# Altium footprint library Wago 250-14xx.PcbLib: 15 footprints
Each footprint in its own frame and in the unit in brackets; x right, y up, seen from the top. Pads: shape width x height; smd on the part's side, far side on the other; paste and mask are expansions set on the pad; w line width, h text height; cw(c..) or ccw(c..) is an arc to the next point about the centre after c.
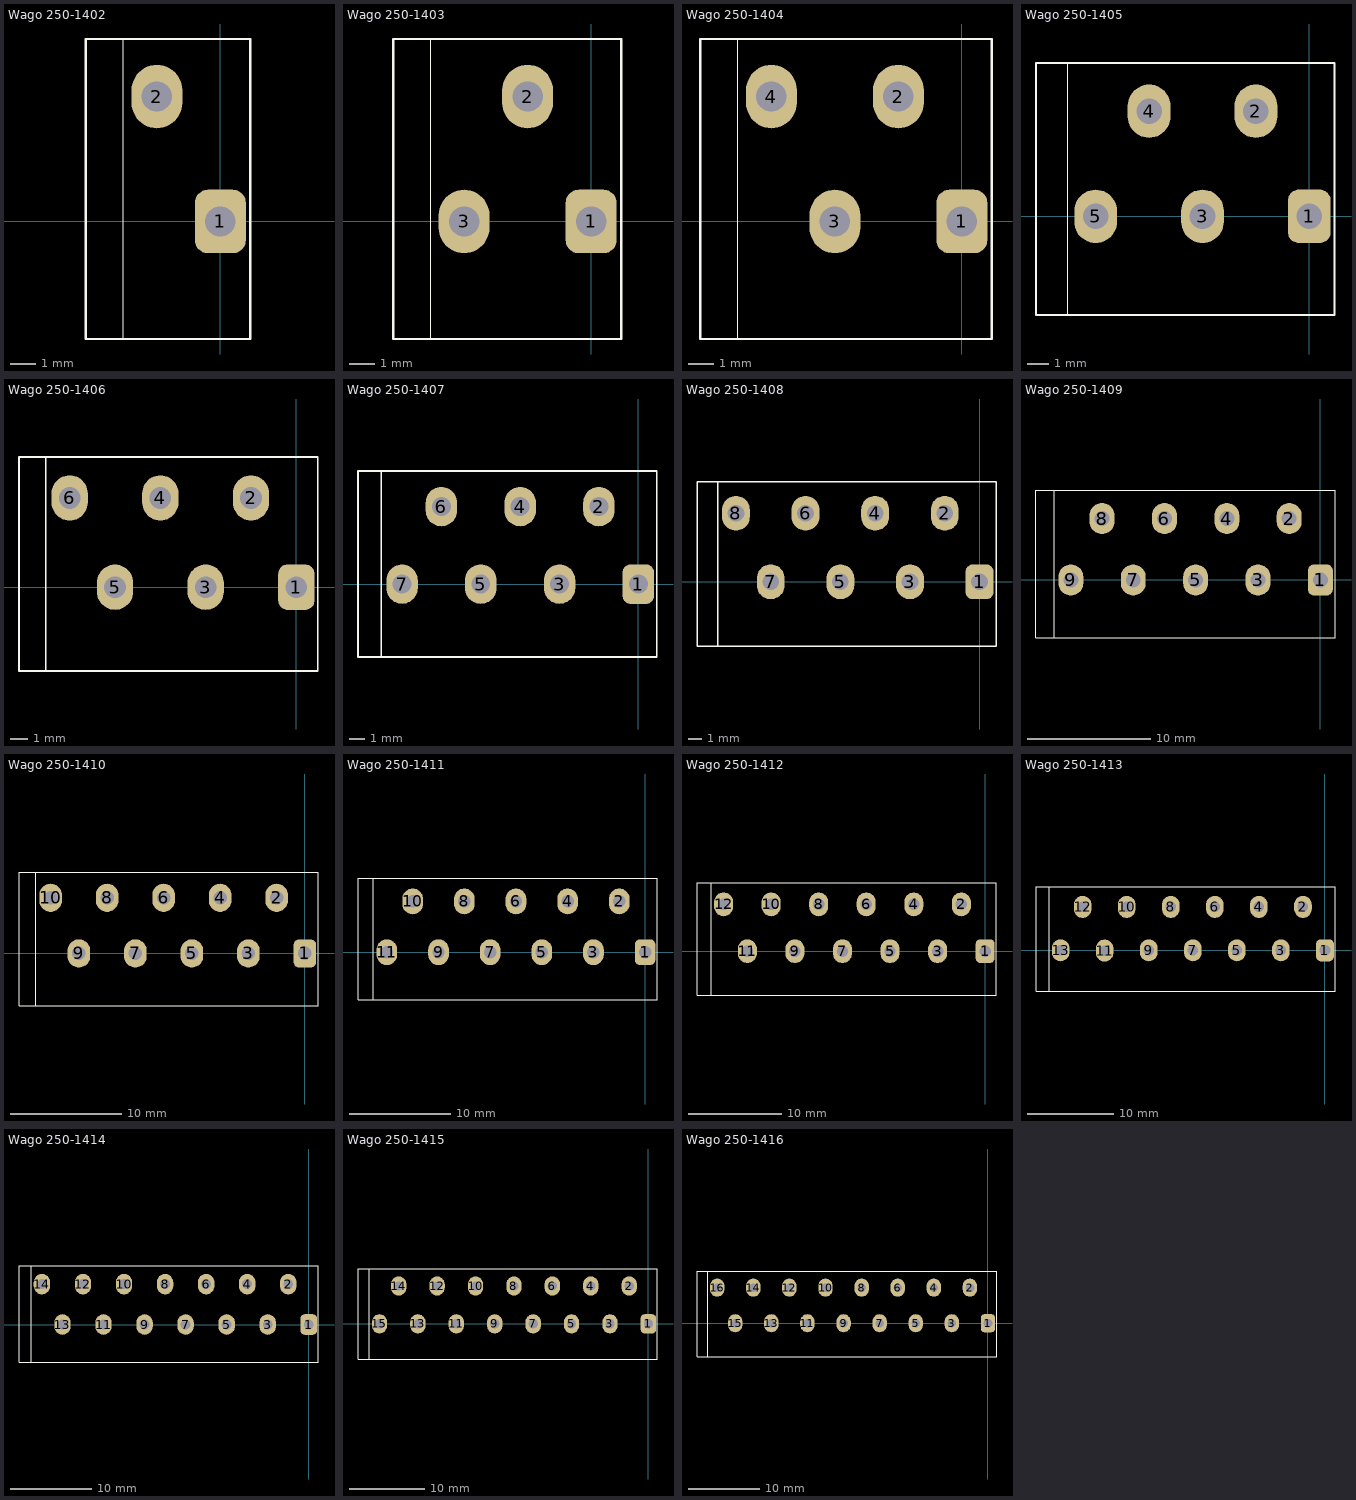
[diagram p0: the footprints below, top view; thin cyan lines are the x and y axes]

## Wago 250-1402 [mil]
height 515.75
pads (2):
  rrect50% 80x100 hole 48: 1(0,0)
  oval 80x100 hole 48: 2(-100,196.85)
Top Overlay:
  lines w0.39: -152.76,-185.04 -152.76,287.4
  lines w3.94: -211.81,-185.04 47.24,-185.04 47.24,287.4 -211.81,287.4 -211.81,-185.04
  text ".Designator" at -206,-249.67 h34
3D body "250-1402.stp": height 515.75, standoff -141.73, extent -212.06,-185.22 47,287.22

## Wago 250-1403 [mil]
height 515.75
pads (3):
  rrect50% 80x100 hole 48: 1(0,0)
  oval 80x100 hole 48: 2(-100,196.85) 3(-200,0)
Top Overlay:
  lines w0.39: -252.76,-185.04 -252.76,287.4
  lines w3.94: -311.81,-185.04 47.24,-185.04 47.24,287.4 -311.81,287.4 -311.81,-185.04
  text ".Designator" at -306,-249.67 h34
3D body "250-1403.stp": height 515.75, standoff -141.73, extent -312.06,-185.22 47,287.22

## Wago 250-1404 [mil]
height 515.75
pads (4):
  rrect50% 80x100 hole 48: 1(0,0)
  oval 80x100 hole 48: 2(-100,196.85) 3(-200,0) 4(-300,196.85)
Top Overlay:
  lines w0.39: -352.76,-185.04 -352.76,287.4
  lines w3.94: -411.81,-185.04 47.24,-185.04 47.24,287.4 -411.81,287.4 -411.81,-185.04
  text ".Designator" at -406,-249.67 h34
3D body "250-1404.stp": height 515.75, standoff -141.73, extent -412.06,-185.22 47,287.22

## Wago 250-1405 [mil]
height 515.75
pads (5):
  rrect50% 80x100 hole 48: 1(0,0)
  oval 80x100 hole 48: 2(-100,196.85) 3(-200,0) 4(-300,196.85) 5(-400,0)
Top Overlay:
  lines w0.39: -452.76,-185.04 -452.76,287.4
  lines w3.94: -511.81,-185.04 -511.81,287.4 47.24,287.4 47.24,-185.04 -511.81,-185.04
  text ".Designator" at -506,-249.67 h34
3D body "250-1405.stp": height 515.75, standoff -141.73, extent -512.06,-185.22 47,287.22

## Wago 250-1406 [mil]
height 515.75
pads (6):
  rrect50% 80x100 hole 48: 1(0,0)
  oval 80x100 hole 48: 2(-100,196.85) 3(-200,0) 4(-300,196.85) 5(-400,0) 6(-500,196.85)
Top Overlay:
  lines w3.94: -552.76,-185.04 -552.76,287.4 ; -611.81,-185.04 -611.81,287.4 47.24,287.4 47.24,-185.04 -611.81,-185.04
  text ".Designator" at -606,-249.67 h34
3D body "250-1406.stp": height 515.75, standoff -141.73, extent -612.06,-185.22 47,287.22

## Wago 250-1407 [mil]
height 515.75
pads (7):
  rrect50% 80x100 hole 48: 1(0,0)
  oval 80x100 hole 48: 2(-100,196.85) 3(-200,0) 4(-300,196.85) 5(-400,0) 6(-500,196.85) 7(-600,0)
Top Overlay:
  lines w3.94: -652.76,-185.04 -652.76,287.4 ; -711.81,-185.04 -711.81,287.4 47.24,287.4 47.24,-185.04 -711.81,-185.04
  text ".Designator" at -706,-249.67 h34
3D body "250-1407.stp": height 515.75, standoff -141.73, extent -712.06,-185.22 47,287.22

## Wago 250-1408 [mil]
height 515.75
pads (8):
  rrect50% 80x100 hole 48: 1(0,0)
  oval 80x100 hole 48: 2(-100,196.85) 3(-200,0) 4(-300,196.85) 5(-400,0) 6(-500,196.85) 7(-600,0) 8(-700,196.85)
Top Overlay:
  lines w3.94: -752.76,-185.04 -752.76,287.4 ; -811.81,-185.04 -811.81,287.4 47.24,287.4 47.24,-185.04 -811.81,-185.04
  text ".Designator" at -806,-249.67 h34
3D body "250-1408.stp": height 515.75, standoff -141.73, extent -812.06,-185.22 47,287.22

## Wago 250-1409 [mil]
height 515.75
pads (9):
  rrect50% 80x100 hole 48: 1(0,0)
  oval 80x100 hole 48: 2(-100,196.85) 3(-200,0) 4(-300,196.85) 5(-400,0) 6(-500,196.85) 7(-600,0) 8(-700,196.85) 9(-800,0)
Top Overlay:
  lines w3.94: -852.76,-185.04 -852.76,287.4 ; -911.81,-185.04 -911.81,287.4 47.24,287.4 47.24,-185.04 -911.81,-185.04
  text ".Designator" at -906,-249.67 h34
3D body "250-1409.stp": height 515.75, standoff -141.73, extent -912.06,-185.22 47,287.22

## Wago 250-1410 [mil]
height 515.75
pads (10):
  rrect50% 80x100 hole 48: 1(0,0)
  oval 80x100 hole 48: 2(-100,196.85) 3(-200,0) 4(-300,196.85) 5(-400,0) 6(-500,196.85) 7(-600,0) 8(-700,196.85) 9(-800,0) 10(-900,196.85)
Top Overlay:
  lines w3.94: -952.76,-185.04 -952.76,287.4 ; -1011.81,-185.04 -1011.81,287.4 47.24,287.4 47.24,-185.04 -1011.81,-185.04
  text ".Designator" at -1006,-249.67 h34
3D body "250-1410.stp": height 515.75, standoff -141.73, extent -1012.06,-185.22 47,287.22

## Wago 250-1411 [mil]
height 515.75
pads (11):
  rrect50% 80x100 hole 48: 1(0,0)
  oval 80x100 hole 48: 2(-100,196.85) 3(-200,0) 4(-300,196.85) 5(-400,0) 6(-500,196.85) 7(-600,0) 8(-700,196.85) 9(-800,0) 10(-900,196.85) 11(-1000,0)
Top Overlay:
  lines w3.94: -1052.76,-185.04 -1052.76,287.4 ; -1111.81,-185.04 -1111.81,287.4 47.24,287.4 47.24,-185.04 -1111.81,-185.04
  text ".Designator" at -1106,-249.67 h34
3D body "250-1411.stp": height 515.75, standoff -141.73, extent -1112.06,-185.22 47,287.22

## Wago 250-1412 [mil]
height 515.75
pads (12):
  rrect50% 80x100 hole 48: 1(0,0)
  oval 80x100 hole 48: 2(-100,196.85) 3(-200,0) 4(-300,196.85) 5(-400,0) 6(-500,196.85) 7(-600,0) 8(-700,196.85) 9(-800,0) 10(-900,196.85) 11(-1000,0) 12(-1100,196.85)
Top Overlay:
  lines w3.94: -1152.76,-185.04 -1152.76,287.4 ; -1211.81,-185.04 47.24,-185.04 47.24,287.4 -1211.81,287.4 -1211.81,-185.04
  text ".Designator" at -1206,-249.67 h34
3D body "250-1412.stp": height 515.75, standoff -141.73, extent -1212.06,-185.22 47,287.22

## Wago 250-1413 [mil]
height 515.75
pads (13):
  rrect50% 80x100 hole 48: 1(0,0)
  oval 80x100 hole 48: 2(-100,196.85) 3(-200,0) 4(-300,196.85) 5(-400,0) 6(-500,196.85) 7(-600,0) 8(-700,196.85) 9(-800,0) 10(-900,196.85) 11(-1000.01,-1.24) 12(-1100,196.85) 13(-1200,0)
Top Overlay:
  lines w3.94: -1252.76,-185.04 -1252.76,287.4 ; -1311.81,-185.04 -1311.81,287.4 47.24,287.4 47.24,-185.04 -1311.81,-185.04
  text ".Designator" at -1306,-249.67 h34
3D body "250-1413.stp": height 515.75, standoff -141.73, extent -1312.06,-185.22 47,287.22

## Wago 250-1414 [mil]
height 515.75
pads (14):
  rrect50% 80x100 hole 48: 1(0,0)
  oval 80x100 hole 48: 2(-100,196.85) 3(-200,0) 4(-300,196.85) 5(-400,0) 6(-500,196.85) 7(-600,0) 8(-700,196.85) 9(-800,0) 10(-900,196.85) 11(-1000,0) 12(-1100,196.85) 13(-1200,0) 14(-1300,196.85)
Top Overlay:
  lines w3.94: -1352.76,-185.04 -1352.76,287.4 ; -1411.81,-185.04 47.24,-185.04 47.24,287.4 -1411.81,287.4 -1411.81,-185.04
  text ".Designator" at -1406,-249.67 h34
3D body "250-1414.stp": height 515.75, standoff -141.73, extent -1412.06,-185.22 47,287.22

## Wago 250-1415 [mil]
height 515.75
pads (15):
  rrect50% 80x100 hole 48: 1(0,0)
  oval 80x100 hole 48: 2(-100,196.85) 3(-200,0) 4(-300,196.85) 5(-400,0) 6(-500,196.85) 7(-600,0) 8(-700,196.85) 9(-800,0) 10(-900,196.85) 11(-1000,0) 12(-1100,196.85) 13(-1200,0) 14(-1300,196.85) 15(-1400,0)
Top Overlay:
  lines w3.94: -1452.76,-185.04 -1452.76,287.4 ; -1511.81,-185.04 -1511.81,287.4 47.24,287.4 47.24,-185.04 -1511.81,-185.04
  text ".Designator" at -1510,-265 h34
3D body "250-1415.stp": height 515.75, standoff -141.73, extent -1512.06,-185.22 47,287.22

## Wago 250-1416 [mil]
height 515.75
pads (16):
  rrect50% 80x100 hole 48: 1(0,0)
  oval 80x100 hole 48: 2(-100,196.85) 3(-200,0) 4(-300,196.85) 5(-400,0) 6(-500,196.85) 7(-600,0) 8(-700,196.85) 9(-800,0) 10(-900,196.85) 11(-1000,0) 12(-1100,196.85) 13(-1200,0) 14(-1300,196.85) 15(-1400,0) 16(-1500,196.85)
Top Overlay:
  lines w3.94: -1552.76,-185.04 -1552.76,287.4 ; -1611.81,-185.04 -1611.81,287.4 47.24,287.4 47.24,-185.04 -1611.81,-185.04
  text ".Designator" at -1606,-249.67 h34
3D body "250-1416.stp": height 515.75, standoff -141.73, extent -1612.06,-185.22 47,287.22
